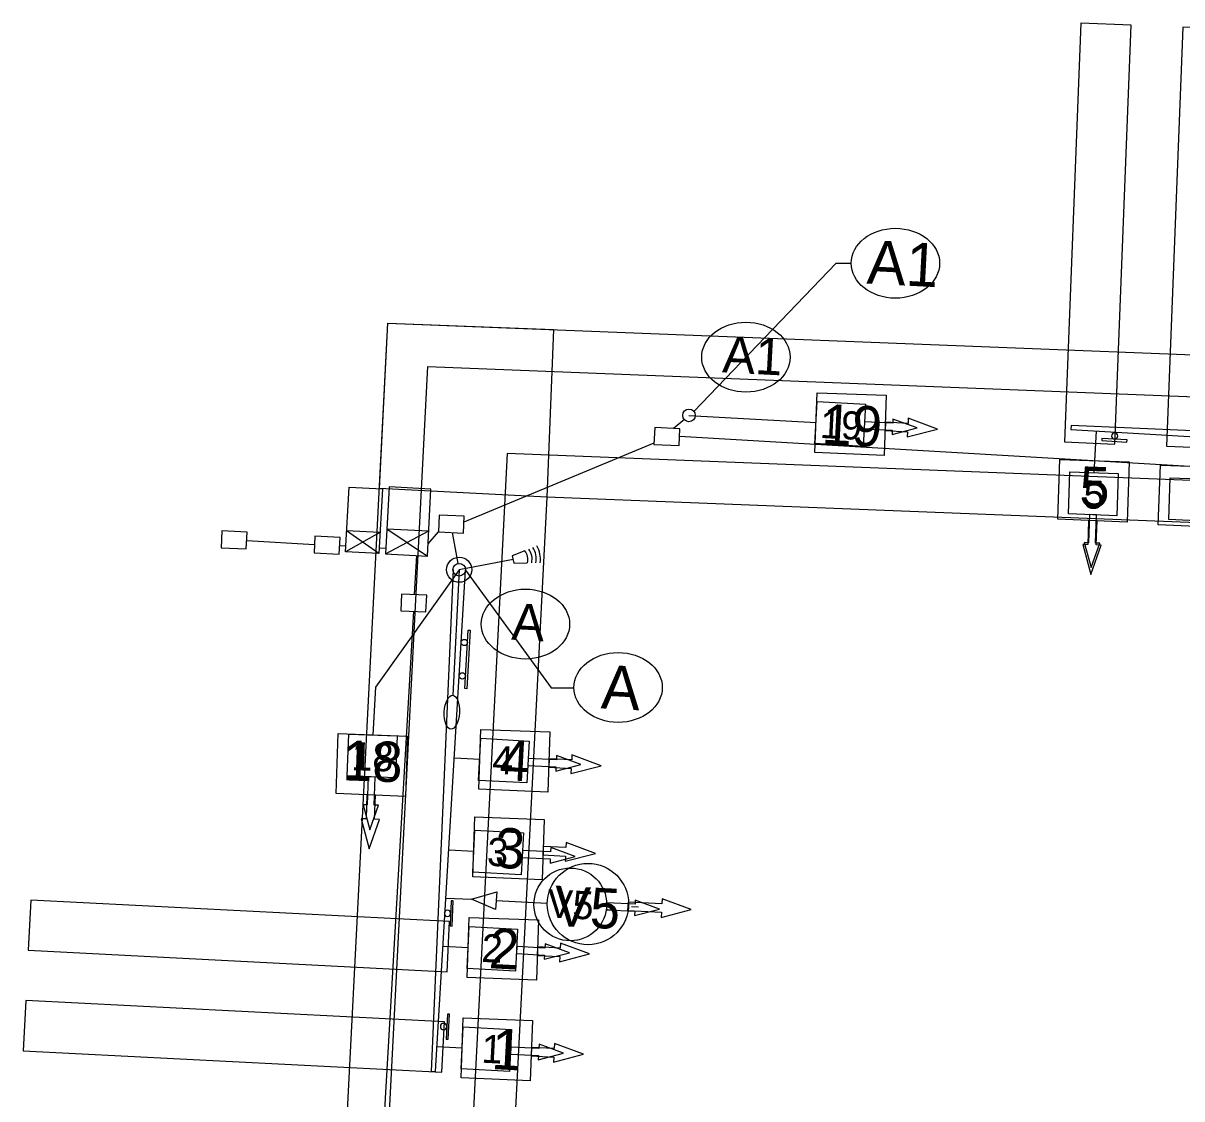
# Model space of a CAD drawing. Extents: x 21 to 686546, y 24 to 735466.
# Drawn here: x 680849.3 to 680987.4, y 735130.9 to 735259.3 of the extents above; entities that cross this region are included whole.
import ezdxf

# ---------------------------------------------------------------- set-up
doc = ezdxf.new("R2010")
doc.units = 0
for name, color, linetype in [('PEDXLIMITS-PR', 7, 'Continuous'), ('signal wiring diagram', 7, 'Continuous'), ('SIGNAL-PLAN VIEW LABLES', 7, 'Continuous'), ('SIGNAL-PR', 7, 'Continuous'), ('signal-pr-conduit', 7, 'Continuous'), ('Video-Zones-pr', 7, 'Continuous')]:
    doc.layers.add(name, color=color, linetype=linetype)

# ---------------------------------------------------------------- blocks, each defined once
blk = doc.blocks.new('STREET NAME SIGN')
at = {"layer": 'SIGNAL-PR'}
blk.add_lwpolyline([(1.5, 0.96), (1.49, 0.71), (-5.5, 0.9), (-5.5, 1.15)], close=True, dxfattribs=at)
for centre in [(-4, 0.49), (-0.01, 0.37)]:
    blk.add_circle(centre, 0.375, dxfattribs=at)
blk = doc.blocks.new('R10-12 SIGN')
at = {"layer": 'SIGNAL-PR'}
blk.add_lwpolyline([(1.52, 0.75), (-1.48, 0.75), (-1.48, 1), (1.52, 1), (1.52, 0.75)], close=True, dxfattribs=at)
blk.add_circle((0.02, 0.37), 0.375, dxfattribs=at)
blk = doc.blocks.new('antenna')
at = {"layer": 'SIGNAL-PR'}
blk.add_lwpolyline([(3.26, 1.25), (0.06, 0.86), (-0.06, -0.86), (3.06, -1.68)], dxfattribs=at)
blk.add_lwpolyline([(3.26, 1.25), (0.06, 0.86), (-0.06, -0.86), (3.06, -1.68)], dxfattribs=at)
for radius, start, end in [(3.08, 327.5887, 24.614), (3.08, 327.5887, 24.614), (4.08, 332.0194, 20.1833), (5.08, 334.664, 17.5387), (6.08, 336.4251, 15.7775)]:
    blk.add_arc((0.47, -0.03), radius, start, end, dxfattribs=at)

msp = doc.modelspace()

# ---------------------------------------------------------------- linework, layer by layer
at = {"layer": 'PEDXLIMITS-PR'}
for points in [[(681056.26, 735053.96), (680884.52, 735062.77), (680892.76, 735223.49), (681064.67, 735216.71)], [(680911.72, 735202.73), (680891.75, 735203.75), (680892.76, 735223.49), (680912.51, 735222.71)], [(681051.53, 735059.21), (680889.77, 735067.5), (680897.5, 735218.3), (681059.42, 735211.91)], [(680906.98, 735207.92), (680900.27, 735076.98), (681042.06, 735069.71), (681048.91, 735202.32)], [(680911.72, 735202.73), (680905.52, 735081.72), (681037.32, 735074.96), (681043.65, 735197.52)]]:
    msp.add_lwpolyline(points, close=True, dxfattribs=at)
at = {"layer": 'signal wiring diagram'}
for points in [[(680943.68, 735209.12), (680943.94, 735214.11), (680949.71, 735213.81), (680949.45, 735208.77)], [(680973.91, 735200.75), (680974.08, 735205.74), (680979.86, 735205.54), (680979.69, 735200.5)], [(680985.89, 735200.04), (680986.06, 735205.03), (680991.84, 735204.83), (680991.66, 735199.79)], [(680887.91, 735169.47), (680888.08, 735174.46), (680893.86, 735174.26), (680893.68, 735169.22)], [(680909.6, 735173.63), (680909.34, 735168.64), (680903.57, 735168.94), (680903.83, 735173.97)], [(680908.91, 735162.66), (680908.66, 735157.67), (680902.88, 735157.97), (680903.14, 735163)], [(680902.71, 735154.75), (680905.73, 735155.63), (680905.6, 735153.55)], [(680908.23, 735151.18), (680907.97, 735146.19), (680902.2, 735146.49), (680902.46, 735151.52)], [(680907.51, 735139.2), (680907.25, 735134.22), (680901.48, 735134.51), (680901.74, 735139.55)]]:
    msp.add_lwpolyline(points, close=True, dxfattribs=at)
for points in [[(680928.66, 735212.47), (680943.81, 735211.61)], [(680952.91, 735210.7), (680952.89, 735210.2), (680955.88, 735210.97), (680952.98, 735212.04), (680952.96, 735211.54), (680949.6, 735211.71), (680949.56, 735210.87), (680952.91, 735210.7)], [(680949.56, 735210.87), (680952.91, 735210.7), (680952.89, 735210.2), (680955.88, 735210.97), (680952.98, 735212.04), (680952.96, 735211.54), (680949.6, 735211.71)], [(680977.21, 735210.6), (680976.96, 735205.64)], [(680976.3, 735197.28), (680975.8, 735197.3), (680976.62, 735194.32), (680977.64, 735197.23), (680977.14, 735197.25), (680977.25, 735200.61), (680976.42, 735200.64), (680976.3, 735197.28)], [(680976.42, 735200.64), (680976.3, 735197.28), (680975.8, 735197.3), (680976.62, 735194.32), (680977.64, 735197.23), (680977.14, 735197.25), (680977.25, 735200.61)], [(680901.26, 735194.06), (680891.26, 735180.05), (680890.97, 735174.36)], [(680900.7, 735171.61), (680903.7, 735171.46)], [(680912.8, 735170.55), (680912.78, 735170.04), (680915.77, 735170.81), (680912.87, 735171.89), (680912.85, 735171.38), (680909.49, 735171.56), (680909.45, 735170.72), (680912.8, 735170.55)], [(680909.45, 735170.72), (680912.8, 735170.55), (680912.78, 735170.04), (680915.77, 735170.81), (680912.87, 735171.89), (680912.85, 735171.38), (680909.49, 735171.56)], [(680890.3, 735166), (680889.79, 735166.02), (680890.61, 735163.04), (680891.64, 735165.96), (680891.13, 735165.97), (680891.25, 735169.33), (680890.41, 735169.36), (680890.3, 735166)], [(680890.41, 735169.36), (680890.3, 735166), (680889.79, 735166.02), (680890.61, 735163.04), (680891.64, 735165.96), (680891.13, 735165.97), (680891.25, 735169.33)], [(680900.02, 735160.64), (680903.01, 735160.49)], [(680912.12, 735159.58), (680912.09, 735159.07), (680915.08, 735159.84), (680912.19, 735160.92), (680912.16, 735160.41), (680908.81, 735160.59), (680908.76, 735159.75), (680912.12, 735159.58)], [(680908.76, 735159.75), (680912.12, 735159.58), (680912.09, 735159.07), (680915.08, 735159.84), (680912.19, 735160.92), (680912.16, 735160.41), (680908.81, 735160.59)], [(680899.67, 735154.9), (680902.71, 735154.75)], [(680905.67, 735154.59), (680910.18, 735154.36)], [(680922.19, 735153.32), (680922.16, 735152.82), (680925.15, 735153.59), (680922.26, 735154.66), (680922.23, 735154.16), (680918.87, 735154.33), (680918.83, 735153.49), (680922.19, 735153.32)], [(680918.83, 735153.49), (680922.19, 735153.32), (680922.16, 735152.82), (680925.15, 735153.59), (680922.26, 735154.66), (680922.23, 735154.16), (680918.87, 735154.33)], [(680918.95, 735153.54), (680919.63, 735153.51)], [(680899.33, 735149.16), (680902.33, 735149.01)], [(680911.43, 735148.1), (680911.41, 735147.59), (680914.4, 735148.36), (680911.5, 735149.44), (680911.47, 735148.93), (680908.12, 735149.11), (680908.08, 735148.27), (680911.43, 735148.1)], [(680908.08, 735148.27), (680911.43, 735148.1), (680911.41, 735147.59), (680914.4, 735148.36), (680911.5, 735149.44), (680911.47, 735148.93), (680908.12, 735149.11)], [(680898.61, 735137.18), (680901.61, 735137.03)], [(680910.71, 735136.12), (680910.69, 735135.61), (680913.68, 735136.39), (680910.78, 735137.46), (680910.76, 735136.96), (680907.4, 735137.13), (680907.36, 735136.29), (680910.71, 735136.12)], [(680907.36, 735136.29), (680910.71, 735136.12), (680910.69, 735135.61), (680913.68, 735136.39), (680910.78, 735137.46), (680910.76, 735136.96), (680907.4, 735137.13)]]:
    msp.add_lwpolyline(points, dxfattribs=at)
msp.add_circle((680914.51, 735154.14), 4.34, dxfattribs=at)
for centre in [(680935.45, 735219.42), (680909.16, 735187.58)]:
    msp.add_ellipse(centre, major_axis=(-5.27, 0), ratio=0.790685, dxfattribs=at)
at = {"layer": 'SIGNAL-PLAN VIEW LABLES'}
for p, q in [((680952.08, 735211.66), (680952.04, 735210.66)), ((680954.79, 735211.52), (680952.08, 735211.66)), ((680954.82, 735212.13), (680954.79, 735211.52)), ((680958.29, 735210.84), (680954.82, 735212.13)), ((680952.04, 735210.66), (680954.73, 735210.52)), ((680954.7, 735209.91), (680958.29, 735210.84)), ((680954.73, 735210.52), (680954.7, 735209.91)), ((680976.32, 735199.94), (680976.22, 735197.06)), ((680977.33, 735199.9), (680976.32, 735199.94)), ((680977.23, 735197.02), (680977.33, 735199.9)), ((680976.22, 735197.06), (680975.62, 735197.08)), ((680975.62, 735197.08), (680976.6, 735193.5)), ((680976.6, 735193.5), (680977.83, 735197)), ((680977.83, 735197), (680977.23, 735197.02)), ((680911.97, 735171.51), (680911.93, 735170.5)), ((680914.68, 735171.37), (680911.97, 735171.51)), ((680914.71, 735171.97), (680914.68, 735171.37)), ((680918.19, 735170.68), (680914.71, 735171.97)), ((680911.93, 735170.5), (680914.62, 735170.36)), ((680914.59, 735169.76), (680918.19, 735170.68)), ((680914.62, 735170.36), (680914.59, 735169.76)), ((680890.26, 735167.22), (680890.16, 735164.33)), ((680891.27, 735167.17), (680890.26, 735167.22)), ((680891.17, 735164.3), (680891.27, 735167.17)), ((680890.16, 735164.33), (680889.56, 735164.35)), ((680889.56, 735164.35), (680890.54, 735160.78)), ((680890.54, 735160.78), (680891.77, 735164.28)), ((680891.77, 735164.28), (680891.17, 735164.3)), ((680914.02, 735161.52), (680913.99, 735160.91)), ((680917.5, 735160.23), (680914.02, 735161.52)), ((680911.28, 735161.05), (680911.25, 735160.05)), ((680911.25, 735160.05), (680913.94, 735159.91)), ((680913.99, 735160.91), (680911.28, 735161.05)), ((680913.91, 735159.3), (680917.5, 735160.23)), ((680913.94, 735159.91), (680913.91, 735159.3)), ((680910.59, 735149.06), (680910.56, 735148.05)), ((680913.3, 735148.92), (680910.59, 735149.06)), ((680913.33, 735149.52), (680913.3, 735148.92)), ((680916.81, 735148.24), (680913.33, 735149.52)), ((680910.56, 735148.05), (680913.25, 735147.91)), ((680913.22, 735147.31), (680916.81, 735148.24)), ((680913.25, 735147.91), (680913.22, 735147.31)), ((680909.88, 735137.08), (680909.84, 735136.07)), ((680912.59, 735136.94), (680909.88, 735137.08)), ((680912.62, 735137.55), (680912.59, 735136.94)), ((680916.1, 735136.26), (680912.62, 735137.55)), ((680909.84, 735136.07), (680912.54, 735135.93)), ((680912.5, 735135.33), (680916.1, 735136.26)), ((680912.54, 735135.93), (680912.5, 735135.33))]:
    msp.add_line(p, q, dxfattribs=at)
for points in [[(680929.25, 735212.93), (680946.23, 735230.62), (680948.01, 735230.62)], [(680928.66, 735212.47), (680943.81, 735211.61)], [(680952.04, 735210.66), (680954.73, 735210.52), (680954.7, 735209.91), (680958.29, 735210.84), (680954.82, 735212.13), (680954.79, 735211.52), (680952.08, 735211.66)], [(680977.21, 735210.6), (680977.03, 735207.09)], [(680976.32, 735199.94), (680976.22, 735197.06), (680975.62, 735197.08), (680976.6, 735193.5), (680977.83, 735197), (680977.23, 735197.02), (680977.33, 735199.9)], [(680901.26, 735194.06), (680891.26, 735180.05), (680890.97, 735174.36)], [(680902.01, 735194.01), (680912.21, 735179.96), (680914.94, 735179.96)], [(680900.7, 735171.61), (680903.7, 735171.46)], [(680911.93, 735170.5), (680914.62, 735170.36), (680914.59, 735169.76), (680918.19, 735170.68), (680914.71, 735171.97), (680914.68, 735171.37), (680911.97, 735171.51)], [(680890.26, 735167.22), (680890.16, 735164.33), (680889.56, 735164.35), (680890.54, 735160.78), (680891.77, 735164.28), (680891.17, 735164.3), (680891.27, 735167.17)], [(680911.25, 735160.05), (680913.94, 735159.91), (680913.91, 735159.3), (680917.5, 735160.23), (680914.02, 735161.52), (680913.99, 735160.91), (680911.28, 735161.05)], [(680900.02, 735160.64), (680903.01, 735160.49)], [(680899.67, 735154.9), (680902.71, 735154.75)], [(680905.67, 735154.59), (680911.76, 735154.28)], [(680925.37, 735153.2), (680925.34, 735152.59), (680928.93, 735153.52), (680925.45, 735154.81), (680925.42, 735154.2), (680921.39, 735154.41), (680921.34, 735153.4), (680925.37, 735153.2)], [(680921.34, 735153.4), (680925.37, 735153.2), (680925.34, 735152.59), (680928.93, 735153.52), (680925.45, 735154.81), (680925.42, 735154.2), (680921.39, 735154.41)], [(680921.81, 735153.91), (680922.63, 735153.86)], [(680899.33, 735149.16), (680902.33, 735149.01)], [(680910.56, 735148.05), (680913.25, 735147.91), (680913.22, 735147.31), (680916.81, 735148.24), (680913.33, 735149.52), (680913.3, 735148.92), (680910.59, 735149.06)], [(680898.61, 735137.18), (680901.61, 735137.03)], [(680909.84, 735136.07), (680912.54, 735135.93), (680912.5, 735135.33), (680916.1, 735136.26), (680912.62, 735137.55), (680912.59, 735136.94), (680909.88, 735137.08)]]:
    msp.add_lwpolyline(points, dxfattribs=at)
for points in [[(680943.68, 735208.05), (680943.93, 735215.18), (680952.19, 735214.89), (680951.94, 735207.69)], [(680972.65, 735200.1), (680972.9, 735207.23), (680981.16, 735206.94), (680980.91, 735199.74)], [(680984.63, 735199.4), (680984.88, 735206.54), (680993.14, 735206.25), (680992.89, 735199.05)], [(680886.59, 735167.37), (680886.84, 735174.51), (680895.1, 735174.22), (680894.85, 735167.02)], [(680903.58, 735167.89), (680903.82, 735175.02), (680912.08, 735174.74), (680911.83, 735167.54)], [(680902.89, 735157.43), (680903.14, 735164.57), (680911.39, 735164.28), (680911.14, 735157.08)], [(680902.71, 735154.75), (680905.73, 735155.63), (680905.6, 735153.55)], [(680902.2, 735145.44), (680902.45, 735152.57), (680910.71, 735152.29), (680910.46, 735145.09)], [(680901.49, 735133.46), (680901.73, 735140.6), (680909.99, 735140.31), (680909.74, 735133.11)]]:
    msp.add_lwpolyline(points, close=True, dxfattribs=at)
msp.add_circle((680916.61, 735154.18), 4.85, dxfattribs=at)
for centre in [(680953.28, 735230.62), (680920.21, 735180.02)]:
    msp.add_ellipse(centre, major_axis=(-5.27, 0), ratio=0.790685, dxfattribs=at)
at = {"layer": 'SIGNAL-PR'}
for p, q in [((680891.81, 735198.49), (680887.82, 735198.69)), ((680891.68, 735195.99), (680887.82, 735198.69)), ((680892.48, 735195.95), (680897.63, 735198.69)), ((680892.64, 735198.95), (680897.48, 735195.69)), ((680892.64, 735198.95), (680897.63, 735198.69)), ((680891.81, 735198.49), (680887.69, 735196.2)), ((680907.68, 735195.28), (680901.26, 735194.06)), ((680901.26, 735194.06), (680900.49, 735179.08))]:
    msp.add_line(p, q, dxfattribs=at)
for points in [[(680924.48, 735209.01), (680927.48, 735208.87), (680927.57, 735210.87), (680924.58, 735211.01)], [(680891.68, 735195.99), (680887.69, 735196.2), (680888.13, 735203.93), (680892.12, 735203.73)], [(680897.48, 735195.69), (680897.89, 735203.68), (680892.89, 735203.94), (680892.48, 735195.95)], [(680898.78, 735198.58), (680901.78, 735198.44), (680901.87, 735200.44), (680898.87, 735200.58)], [(680872.87, 735196.69), (680875.86, 735196.56), (680875.96, 735198.55), (680872.96, 735198.69)], [(680883.96, 735196.06), (680886.96, 735195.93), (680887.05, 735197.92), (680884.05, 735198.06)], [(680894.29, 735189.17), (680897.28, 735189.03), (680897.38, 735191.03), (680894.38, 735191.16)]]:
    msp.add_lwpolyline(points, close=True, dxfattribs=at)
for points in [[(681039.73, 735208.42), (680974.24, 735211.27), (680974.21, 735210.77), (681039.65, 735206.92)], [(680900.52, 735194.09), (680897.91, 735134.21), (680898.44, 735134.19), (680902.01, 735194.02)]]:
    msp.add_lwpolyline(points, dxfattribs=at)
for centre, radius in [((680928.66, 735212.47), 0.75), ((680901.26, 735194.06), 1.5), ((680901.26, 735194.06), 0.75)]:
    msp.add_circle(centre, radius, dxfattribs=at)
msp.add_ellipse((680900.38, 735177.06), major_axis=(0.11, 2.02), ratio=0.447722, dxfattribs=at)
at = {"layer": 'signal-pr-conduit'}
for points in [[(680928.12, 735211.99), (680926.83, 735210.9)], [(680927.53, 735209.98), (681041.77, 735203.28)], [(680901.84, 735199.77), (680924.49, 735209.18)], [(680897.55, 735197.14), (680898.78, 735198.58)], [(680875.93, 735197.56), (680884.01, 735197.09)], [(680900.41, 735198.5), (680901.11, 735194.82)], [(680887.73, 735196.89), (680887.03, 735196.93)], [(680891.74, 735196.69), (680892.52, 735196.65)], [(680896.17, 735195.76), (680895.9, 735191.09)], [(680895.79, 735189.1), (680890.03, 735090)]]:
    msp.add_lwpolyline(points, dxfattribs=at)
at = {"layer": 'Video-Zones-pr'}
for points in [[(680975.4, 735259.26), (680973.43, 735209.3), (680979.43, 735209.06), (680981.4, 735259.02)], [(680987.57, 735258.78), (680985.6, 735208.82), (680991.59, 735208.58), (680993.57, 735258.54)], [(680849.87, 735148.67), (680899.81, 735146.11), (680900.11, 735152.1), (680850.18, 735154.66)], [(680849.26, 735136.69), (680899.19, 735134.13), (680899.5, 735140.12), (680849.57, 735142.68)]]:
    msp.add_lwpolyline(points, close=True, dxfattribs=at)

# ---------------------------------------------------------------- block references
at = {"layer": 'SIGNAL-PR'}
for p, yscale, rotation in [((680979.43, 735210.38), -1, -3.386662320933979), ((680899.49, 735153.08), -1, 87.52168973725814), ((680899.02, 735139.58), -0.9999999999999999, 86.76446857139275)]:
    msp.add_blockref('R10-12 SIGN', p, dxfattribs=dict(at, yscale=yscale, rotation=rotation))
at = {"layer": 'SIGNAL-PR', "xscale": 0.4999999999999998, "yscale": 0.4999999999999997, "rotation": 15.476805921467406}
msp.add_blockref('antenna', (680907.68, 735195.28), dxfattribs=at)
at = {"layer": 'SIGNAL-PR', "rotation": -91.74748873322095}
msp.add_blockref('STREET NAME SIGN', (680901.26, 735181.4), dxfattribs=at)

# ---------------------------------------------------------------- texts
at = {"layer": 'signal wiring diagram'}
for s, height, rotation, p in [('A1', 4.368, 357.0414, (680932.58, 735217.61)), ('19', 3.36, 357.0414, (680944.23, 735209.79)), ('5', 3.36, 357.9965, (680975.65, 735201.38)), ('A', 4.37, 357.0414, (680907.43, 735185.72)), ('18', 3.36, 357.9965, (680888.37, 735170.16)), ('4', 3.36, 357.0414, (680905.14, 735169.74)), ('3', 3.36, 357.0414, (680904.53, 735158.77)), ('V5', 3.36, 357.0414, (680911.71, 735152.6)), ('2', 3.36, 357.0414, (680903.85, 735147.29)), ('1', 3.36, 357.0414, (680903.85, 735135.27))]:
    msp.add_text(s, height=height, rotation=rotation, dxfattribs=at).set_placement(p)
at = {"layer": 'SIGNAL-PLAN VIEW LABLES'}
for s, height, rotation, p in [('A1', 5.2, 357.0414, (680949.8, 735228.2)), ('19', 4.8, 357.0414, (680944.43, 735209.07)), ('5', 4.8, 357.9965, (680975.18, 735201.61)), ('A', 5.2, 357.0414, (680918.1, 735177.53)), ('18', 4.8, 357.9965, (680887.29, 735168.95)), ('4', 4.8, 357.0414, (680905.99, 735169)), ('3', 4.8, 357.0414, (680905.42, 735158.53)), ('V5', 4.8, 357.0414, (680912.49, 735151.59)), ('2', 4.8, 357.0414, (680904.73, 735146.54)), ('1', 4.8, 357.0414, (680905.04, 735134.51))]:
    msp.add_text(s, height=height, rotation=rotation, dxfattribs=at).set_placement(p)

doc.saveas('drawing.dxf')
